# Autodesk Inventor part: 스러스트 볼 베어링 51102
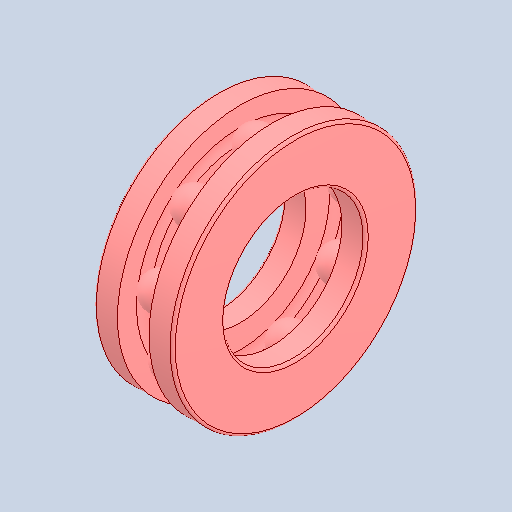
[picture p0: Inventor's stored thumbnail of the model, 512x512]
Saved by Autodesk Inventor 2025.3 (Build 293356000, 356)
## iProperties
Created: 2025-09
Part Number: 스러스트 볼 베어링 51102
Material: 강철, 연강
Description: 롤링 베어링 - 플랫 뒷면이 있는 스러스트 볼 베어링
Document SubType Name: Modeling
Designer: PC-15
Density: 7.85 g/cm^3
Appearance: 기본값
Author: jhkim
Sending System: Autodesk Inventor 2026
Preprocessor: ST-DEVELOPER v20.1
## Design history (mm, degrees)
feature "Solid1"
feature "Solid1:1"
feature "Solid1:2"
feature "Solid1:3"
feature "Solid1:4"
feature "Solid1:5"
feature "Solid1:6"
feature "Solid1:7"
feature "Solid1:8"
feature "Solid1:9"
feature "Solid1:10"
node "솔리드1"
node "솔리드2"
node "솔리드3"
node "솔리드4"
node "솔리드5"
node "솔리드6"
node "솔리드7"
node "솔리드8"
node "솔리드9"
node "솔리드10"
node "솔리드11"
